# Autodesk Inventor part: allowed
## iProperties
Shininess: 64.0
Length Units: 11269
Angle Units: 11279
Time Units: 11290
Mass Units: 11283
Length Display Precision: 3
Angle Display Precision: 2
Compacted: True
Part Number: allowed
Document SubType Name: Modeling
Created: 2004-07
Designer: Peter
Manufacturer: Standard
Standards Organization: Custom
Density: 0.0
Volumn: 0.0
Area: 0.0
PropertySet Name: Model Information
Control State: 0
Master: False
Checked Out: False
Author: Peter
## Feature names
1. Extrusion1
